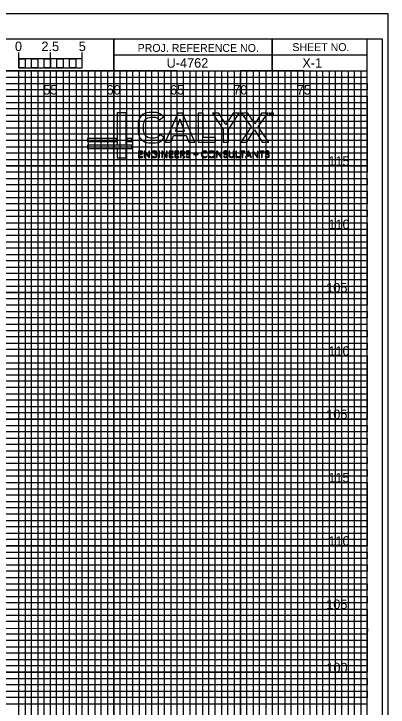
# Model space of a CAD drawing. Extents: x -7 to 162, y -2 to 107.
# Drawn here: x 132.1 to 161.7, y 52.2 to 107 of the extents above; entities that cross this region are included whole.
import ezdxf

# ---------------------------------------------------------------- set-up
doc = ezdxf.new("R2010")
doc.units = 0
for name, color, linetype in [('Old_Level_1', 7, 'Continuous'), ('Prop XS Bar Scale Labels', 7, 'Continuous'), ('Prop XS Elevation Labels', 7, 'Continuous'), ('Prop XS Offset Labels', 7, 'Continuous'), ('Prop XS Project Number', 7, 'Continuous'), ('Prop XS Sheet Number', 7, 'Continuous'), ('Sheet Cross Section CELL', 7, 'Continuous'), ('Sheet Cross Section Grid Major CELL', 7, 'Continuous'), ('Sheet Cross Section Grid Middle CELL', 7, 'Continuous'), ('Sheet Cross Section Grid Minor 1 CELL', 7, 'Continuous'), ('Sheet Cross Section Grid Minor 2 CELL', 7, 'Continuous'), ('Sheet Cross Section Scale CELL', 7, 'Continuous'), ('Sheet Cutting Line CELL', 7, 'Continuous'), ('Sheet DOT Grid CELL', 7, 'Continuous'), ('Sheet Plot Border Inside CELL', 7, 'Continuous'), ('Sheet Plot Border Outside CELL', 7, 'Continuous')]:
    doc.layers.add(name, color=color, linetype=linetype)

msp = doc.modelspace()

# ---------------------------------------------------------------- linework, layer by layer
at = {"layer": 'Old_Level_1'}
for p, q in [((152.376, 99.163), (152.234, 99.163)), ((152.234, 99.163), (152.234, 99.14)), ((152.234, 99.14), (152.293, 99.14)), ((152.293, 99.14), (152.293, 98.986)), ((152.318, 98.986), (152.318, 99.14)), ((152.318, 99.14), (152.376, 99.14)), ((152.376, 99.14), (152.376, 99.163)), ((152.376, 99.14), (152.376, 99.14)), ((152.452, 99.163), (152.412, 99.163)), ((152.412, 99.163), (152.412, 98.986)), ((152.439, 99.135), (152.438, 99.135)), ((152.438, 98.986), (152.439, 99.135)), ((152.439, 99.135), (152.499, 98.986)), ((152.508, 99.027), (152.452, 99.163)), ((152.563, 99.163), (152.508, 99.027)), ((152.515, 98.986), (152.576, 99.135)), ((152.602, 99.163), (152.563, 99.163)), ((152.576, 99.135), (152.575, 99.135)), ((152.576, 99.135), (152.576, 98.986)), ((152.602, 98.986), (152.602, 99.163)), ((143.612, 98.627), (143.928, 98.86)), ((152.293, 98.986), (152.318, 98.986)), ((152.412, 98.986), (152.438, 98.986)), ((152.499, 98.986), (152.515, 98.986)), ((152.576, 98.986), (152.602, 98.986)), ((152.602, 98.986), (152.602, 98.986)), ((143.98, 97.225), (143.644, 97.464)), ((143.358, 96.068), (143.396, 96.106)), ((145.956, 96.077), (146.001, 96.112)), ((147.317, 96.061), (147.362, 96.094)), ((148.928, 96.077), (148.972, 96.112)), ((152.223, 96.077), (152.268, 96.112)), ((145.734, 95.756), (145.688, 95.723)), ((147.374, 95.74), (147.332, 95.77)), ((148.706, 95.756), (148.66, 95.723)), ((152.001, 95.756), (151.955, 95.723))]:
    msp.add_line(p, q, dxfattribs=at)
for points in [[(140.984, 96.665), (140.984, 99.182), (140.267, 99.182), (140.267, 96.665), (140.984, 96.665), (140.984, 96.665)], [(140.984, 96.665), (140.984, 99.182), (140.267, 99.182), (140.267, 96.665), (140.984, 96.665)], [(144.064, 96.876), (144.52, 96.876), (144.726, 97.399), (145.719, 97.399), (145.932, 96.876), (146.397, 96.876), (145.412, 99.163), (145.059, 99.163), (144.064, 96.876)], [(146.652, 96.876), (148.032, 96.876), (148.032, 97.244), (147.06, 97.244), (147.06, 99.163), (146.652, 99.163), (146.652, 96.876)], [(148.64, 96.876), (149.047, 96.876), (149.047, 97.855), (149.906, 99.163), (149.422, 99.163), (148.853, 98.252), (148.291, 99.163), (147.78, 99.163), (148.64, 97.855), (148.64, 96.876)], [(150.023, 96.876), (150.514, 96.876), (151.115, 97.842), (151.719, 96.876), (152.236, 96.876), (151.406, 98.071), (152.155, 99.163), (151.661, 99.163), (151.128, 98.317), (150.588, 99.163), (150.074, 99.163), (150.837, 98.071), (150.023, 96.876)], [(145.576, 97.748), (145.224, 98.679), (144.865, 97.748), (145.576, 97.748)], [(137.929, 97.167), (137.929, 96.928), (140.213, 96.928), (140.213, 97.167), (137.929, 97.167)], [(141.431, 96.928), (141.431, 97.167), (141.028, 97.167), (141.028, 96.928), (141.431, 96.928)], [(137.929, 96.379), (141.431, 96.379), (141.431, 96.619), (137.929, 96.619), (137.929, 96.379)], [(140.267, 95.636), (140.984, 95.636), (140.984, 96.333), (140.267, 96.333), (140.267, 95.636)], [(142.01, 95.897), (142.251, 95.897), (142.251, 95.944), (142.01, 95.944), (142.01, 96.113), (142.268, 96.113), (142.268, 96.16), (141.959, 96.16), (141.959, 95.662), (142.276, 95.662), (142.276, 95.708), (142.01, 95.708), (142.01, 95.897)], [(142.473, 96.16), (142.409, 96.16), (142.409, 95.662), (142.46, 95.662), (142.461, 96.088), (142.758, 95.662), (142.822, 95.662), (142.822, 96.16), (142.771, 96.16), (142.77, 95.738), (142.473, 96.16)], [(143.404, 95.7), (143.404, 95.944), (143.235, 95.944), (143.235, 95.897), (143.354, 95.897), (143.354, 95.731)], [(143.621, 96.16), (143.57, 96.16), (143.57, 95.662), (143.621, 95.662), (143.621, 96.16)], [(143.853, 96.16), (143.789, 96.16), (143.789, 95.662), (143.84, 95.662), (143.841, 96.088), (144.138, 95.662), (144.202, 95.662), (144.202, 96.16), (144.151, 96.16), (144.149, 95.738), (143.853, 96.16)], [(144.42, 95.897), (144.662, 95.897), (144.662, 95.944), (144.42, 95.944), (144.42, 96.113), (144.679, 96.113), (144.679, 96.16), (144.37, 96.16), (144.37, 95.662), (144.687, 95.662), (144.687, 95.708), (144.42, 95.708), (144.42, 95.897)], [(144.871, 95.897), (145.112, 95.897), (145.112, 95.944), (144.871, 95.944), (144.871, 96.113), (145.129, 96.113), (145.129, 96.16), (144.82, 96.16), (144.82, 95.662), (145.137, 95.662), (145.137, 95.708), (144.871, 95.708), (144.871, 95.897)], [(145.424, 96.16), (145.27, 96.16), (145.27, 95.662), (145.321, 95.662), (145.321, 95.893), (145.406, 95.893), (145.542, 95.662), (145.604, 95.662), (145.46, 95.898)], [(145.411, 96.113), (145.321, 96.113), (145.321, 95.94), (145.411, 95.94)], [(146.491, 96.092), (146.449, 96.092), (146.449, 95.933), (146.291, 95.933), (146.291, 95.891), (146.449, 95.891), (146.449, 95.733), (146.491, 95.733), (146.491, 95.891), (146.65, 95.891), (146.65, 95.933), (146.491, 95.933), (146.491, 96.092)], [(148.175, 96.16), (148.112, 96.16), (148.112, 95.662), (148.163, 95.662), (148.164, 96.088), (148.461, 95.662), (148.524, 95.662), (148.524, 96.16), (148.473, 96.16), (148.472, 95.738), (148.175, 96.16)], [(149.159, 95.853), (149.159, 96.16), (149.108, 96.16), (149.108, 95.847)], [(149.473, 95.847), (149.473, 96.16), (149.422, 96.16), (149.422, 95.853)], [(149.683, 96.16), (149.632, 96.16), (149.632, 95.662), (149.915, 95.662), (149.915, 95.708), (149.683, 95.708), (149.683, 96.16)], [(150.177, 96.113), (150.344, 96.113), (150.344, 96.16), (149.96, 96.16), (149.96, 96.113), (150.126, 96.113), (150.126, 95.662), (150.177, 95.662), (150.177, 96.113)], [(150.501, 95.793), (150.755, 95.793), (150.81, 95.662), (150.869, 95.662), (150.653, 96.16), (150.604, 96.16), (150.387, 95.662), (150.446, 95.662), (150.501, 95.793)], [(150.52, 95.839), (150.736, 95.839), (150.628, 96.101), (150.52, 95.839)], [(151.033, 96.16), (150.97, 96.16), (150.97, 95.662), (151.021, 95.662), (151.022, 96.088), (151.319, 95.662), (151.382, 95.662), (151.382, 96.16), (151.332, 96.16), (151.33, 95.738), (151.033, 96.16)], [(151.71, 96.113), (151.877, 96.113), (151.877, 96.16), (151.493, 96.16), (151.493, 96.113), (151.66, 96.113), (151.66, 95.662), (151.71, 95.662), (151.71, 96.113)]]:
    msp.add_lwpolyline(points, dxfattribs=at)
for points in [[(143.928, 98.86), (143.702, 99.121), (143.437, 99.222), (143.127, 99.222), (142.422, 99.222), (141.918, 98.743), (141.918, 98.01), (141.918, 97.296), (142.422, 96.817), (143.127, 96.817), (143.463, 96.817), (143.773, 96.94), (143.98, 97.225)], [(143.644, 97.464), (143.492, 97.27), (143.314, 97.186), (143.13, 97.186), (142.658, 97.186), (142.345, 97.548), (142.345, 98.036), (142.345, 98.491), (142.658, 98.853), (143.13, 98.853), (143.288, 98.853), (143.444, 98.805), (143.612, 98.627)], [(143.396, 96.106), (143.352, 96.15), (143.295, 96.172), (143.216, 96.172), (143.067, 96.172), (142.956, 96.062), (142.956, 95.911), (142.956, 95.759), (143.067, 95.649), (143.216, 95.649), (143.276, 95.649), (143.349, 95.667), (143.404, 95.7)], [(143.354, 95.731), (143.316, 95.71), (143.267, 95.695), (143.216, 95.695), (143.088, 95.695), (143.011, 95.796), (143.011, 95.911), (143.011, 96.025), (143.088, 96.126), (143.216, 96.126), (143.277, 96.126), (143.324, 96.104), (143.358, 96.068)], [(145.411, 95.94), (145.502, 95.94), (145.533, 95.979), (145.533, 96.027), (145.533, 96.075), (145.502, 96.113), (145.411, 96.113)], [(145.46, 95.898), (145.542, 95.905), (145.588, 95.958), (145.588, 96.027), (145.588, 96.116), (145.525, 96.16), (145.424, 96.16)], [(145.688, 95.723), (145.726, 95.671), (145.785, 95.649), (145.845, 95.649), (145.924, 95.649), (146.009, 95.702), (146.009, 95.793), (146.009, 95.973), (145.754, 95.902), (145.754, 96.036), (145.754, 96.099), (145.808, 96.126), (145.86, 96.126), (145.902, 96.126), (145.935, 96.11), (145.956, 96.077)], [(146.001, 96.112), (145.961, 96.157), (145.916, 96.172), (145.86, 96.172), (145.779, 96.172), (145.699, 96.127), (145.699, 96.031), (145.699, 95.849), (145.954, 95.927), (145.954, 95.786), (145.954, 95.728), (145.897, 95.695), (145.847, 95.695), (145.795, 95.695), (145.755, 95.719), (145.734, 95.756)], [(147.362, 96.094), (147.318, 96.149), (147.251, 96.172), (147.189, 96.172), (147.041, 96.172), (146.93, 96.062), (146.93, 95.911), (146.93, 95.759), (147.041, 95.649), (147.189, 95.649), (147.272, 95.649), (147.341, 95.689), (147.374, 95.74)], [(147.332, 95.77), (147.295, 95.712), (147.241, 95.695), (147.189, 95.695), (147.061, 95.695), (146.985, 95.796), (146.985, 95.911), (146.985, 96.025), (147.061, 96.126), (147.189, 96.126), (147.242, 96.126), (147.298, 96.093), (147.317, 96.061)], [(147.718, 95.649), (147.569, 95.649), (147.458, 95.759), (147.458, 95.911), (147.458, 96.062), (147.569, 96.172), (147.718, 96.172), (147.866, 96.172), (147.977, 96.062), (147.977, 95.911), (147.977, 95.759), (147.866, 95.649), (147.718, 95.649), (147.718, 95.649), (147.718, 95.649), (147.718, 95.649)], [(147.718, 96.126), (147.59, 96.126), (147.513, 96.025), (147.513, 95.911), (147.513, 95.796), (147.59, 95.695), (147.718, 95.695), (147.846, 95.695), (147.922, 95.796), (147.922, 95.911), (147.922, 96.025), (147.846, 96.126), (147.718, 96.126), (147.718, 96.126), (147.718, 96.126), (147.718, 96.126)], [(148.66, 95.723), (148.698, 95.671), (148.756, 95.649), (148.817, 95.649), (148.896, 95.649), (148.981, 95.702), (148.981, 95.793), (148.981, 95.973), (148.725, 95.902), (148.725, 96.036), (148.725, 96.099), (148.78, 96.126), (148.832, 96.126), (148.874, 96.126), (148.906, 96.11), (148.928, 96.077)], [(148.972, 96.112), (148.933, 96.157), (148.888, 96.172), (148.832, 96.172), (148.751, 96.172), (148.671, 96.127), (148.671, 96.031), (148.671, 95.849), (148.926, 95.927), (148.926, 95.786), (148.926, 95.728), (148.869, 95.695), (148.819, 95.695), (148.767, 95.695), (148.727, 95.719), (148.706, 95.756)], [(149.108, 95.847), (149.108, 95.764), (149.141, 95.649), (149.29, 95.649), (149.44, 95.649), (149.473, 95.764), (149.473, 95.847)], [(149.422, 95.853), (149.422, 95.71), (149.328, 95.695), (149.29, 95.695), (149.252, 95.695), (149.159, 95.71), (149.159, 95.853)], [(151.955, 95.723), (151.993, 95.671), (152.052, 95.649), (152.112, 95.649), (152.191, 95.649), (152.276, 95.702), (152.276, 95.793), (152.276, 95.973), (152.021, 95.902), (152.021, 96.036), (152.021, 96.099), (152.075, 96.126), (152.127, 96.126), (152.169, 96.126), (152.202, 96.11), (152.223, 96.077)], [(152.268, 96.112), (152.228, 96.157), (152.183, 96.172), (152.127, 96.172), (152.046, 96.172), (151.966, 96.127), (151.966, 96.031), (151.966, 95.849), (152.221, 95.927), (152.221, 95.786), (152.221, 95.728), (152.164, 95.695), (152.114, 95.695), (152.062, 95.695), (152.022, 95.719), (152.001, 95.756)]]:
    msp.add_open_spline(points, degree=3, dxfattribs=at)
at = {"layer": 'Sheet Cross Section CELL'}
for p, q in [((152.5, 105), (152.5, 102.5)), ((152.5, 102.5), (152.5, 105)), ((140, 103.75), (140, 102.5)), ((160, 103.745), (140, 103.745)), ((140, 102.5), (160, 102.5))]:
    msp.add_line(p, q, dxfattribs=at)
for points in [[(160, 105), (0, 105), (0, 0), (160, 0)], [(140, 105), (130, 105), (130, 102.515), (140, 102.515)], [(160, 105), (140, 105), (140, 102.5), (160, 102.5)]]:
    msp.add_lwpolyline(points, close=True, dxfattribs=at)
at = {"layer": 'Sheet Cross Section Grid Major CELL'}
for p, q in [((135, 0), (135, 102.5)), ((145, 102.5), (140, 102.5)), ((140, 102.5), (140, 0)), ((145, 0), (145, 102.5)), ((155, 102.5), (150, 102.5)), ((150, 102.5), (150, 0)), ((155, 0), (155, 102.5))]:
    msp.add_line(p, q, dxfattribs=at)
for points in [[(0, 100), (160, 100), (160, 95), (0, 95)], [(0, 90), (160, 90), (160, 85), (0, 85)], [(0, 80), (160, 80), (160, 75), (0, 75)], [(0, 70), (160, 70), (160, 65), (0, 65)], [(0, 60), (160, 60), (160, 55), (0, 55)]]:
    msp.add_lwpolyline(points, dxfattribs=at)
at = {"layer": 'Sheet Cross Section Grid Middle CELL'}
for points in [[(127.5, 0), (127.5, 105), (129.965, 105), (130, 105), (130, 102.5), (132.495, 102.5), (132.495, 0)], [(0, 102.5), (137.5, 102.5)], [(137.5, 0), (137.5, 102.5), (142.5, 102.5), (142.5, 0)], [(147.5, 0), (147.5, 102.5), (152.5, 102.5), (152.5, 0)], [(157.5, 0), (157.5, 102.5)], [(0, 92.5), (160, 92.5), (160, 97.5), (0, 97.5)], [(0, 82.5), (160, 82.5), (160, 87.5), (0, 87.5)], [(0, 72.5), (160, 72.5), (160, 77.5), (0, 77.5)], [(0, 62.5), (160, 62.5), (160, 67.5), (0, 67.5)], [(0, 52.5), (160, 52.5), (160, 57.5), (0, 57.5)]]:
    msp.add_lwpolyline(points, dxfattribs=at)
at = {"layer": 'Sheet Cross Section Grid Minor 1 CELL'}
msp.add_line((0, 102), (160, 102), dxfattribs=at)
for points in [[(0, 101.5), (135, 101.5), (160, 101.5), (160, 101), (0, 101)], [(0, 100.5), (160, 100.5), (160, 99.5), (0, 99.5)], [(0, 99), (160, 99), (160, 98.5), (0, 98.49)], [(0, 98), (160, 98), (160, 97), (0, 97)], [(0, 96.5), (160, 96.5), (160, 96), (0, 96)], [(0, 95.5), (160, 95.5), (160, 94.5), (0, 94.5)], [(0, 94), (160, 94), (160, 93.5), (0, 93.5)], [(0, 93), (160, 93), (160, 92), (0, 92)], [(0, 91.5), (160, 91.5), (160, 91), (0, 91)], [(0, 90.5), (160, 90.5), (160, 89.5), (0, 89.5)], [(0, 89), (160, 89), (160, 88.5), (0, 88.5)], [(0, 88), (160, 88), (160, 86.975), (160, 86.5), (160, 86), (0, 86)], [(0, 87), (160, 87), (160, 86.5), (0, 86.5)], [(0, 85.5), (160, 85.5), (160, 84.5), (0, 84.515)], [(0, 84.515), (160, 84.5), (160, 84), (0, 84)], [(0, 83.5), (160, 83.5), (160, 83), (0, 83)], [(0, 82), (160, 82), (160, 81.5), (0, 81.5)], [(0, 81), (160, 81), (160, 80.5), (0, 80.5)], [(-0.035, 79.445), (160, 79.445), (160, 78.94), (-0.035, 78.94)], [(0, 78.5), (160, 78.5), (160, 78), (0, 78)], [(0, 77), (160, 77), (160, 76.5), (0, 76.5)], [(0, 76), (160, 76), (160, 75.5), (0, 75.5)], [(0, 74.5), (160, 74.5), (160, 74), (0, 74)], [(0, 73.5), (160, 73.5), (160, 73), (0, 73)], [(0, 72), (160, 72), (160, 71.5), (0, 71.5)], [(0, 71), (160, 71), (160, 70.5), (0, 70.5)], [(0, 69.5), (160, 69.5), (159.995, 68.99), (0, 69)], [(0, 68.5), (160, 68.5), (160, 68), (0, 68)], [(0, 67), (160, 67), (160, 66.5), (0, 66.5)], [(0, 66), (160, 66), (160, 65.5), (0, 65.5)], [(0, 64.5), (160, 64.5), (160, 64), (0, 64)], [(0, 63.5), (160, 63.5), (160, 63), (0, 63)], [(0, 62), (160, 62), (160, 61.5), (0, 61.5)], [(0, 61), (160, 61), (160, 60.5), (0, 60.5)], [(0, 59.5), (160, 59.5), (160, 59), (0, 59)], [(0, 58.495), (160.035, 58.455), (160, 58), (0, 58)], [(0, 57), (160, 57), (160, 56.5), (0, 56.5)], [(0, 56), (160, 56), (160, 55.5), (0, 55.5)], [(0, 54.5), (160, 54.5), (160, 54), (0, 54)], [(0, 53.5), (160, 53.5), (160, 53), (0, 53)]]:
    msp.add_lwpolyline(points, dxfattribs=at)
at = {"layer": 'Sheet Cross Section Grid Minor 2 CELL'}
for p, q in [((133.5, 102.5), (133.005, 102.5)), ((133.005, 102.5), (133.005, 0)), ((133.5, 0), (133.5, 102.5)), ((134.5, 102.5), (134, 102.5)), ((134, 102.5), (134, 0)), ((134.5, 0), (134.5, 102.5))]:
    msp.add_line(p, q, dxfattribs=at)
for points in [[(135, 0), (135.49, 0), (135.49, 102.5), (136, 102.5), (136, 0)], [(136, 0), (136.5, 0), (136.5, 102.5), (137.025, 102.5), (137.025, 0)], [(137.5, 0), (138, 0), (138, 102.5), (138.5, 102.5), (138.5, 0)], [(138.5, 0), (139, 0), (139, 102.5), (139.5, 102.5), (139.5, 0)], [(140, 0), (140.5, 0), (140.5, 102.5), (141, 102.5), (141, 0)], [(141, 0), (141.5, 0), (141.5, 102.5), (142, 102.5), (142, 0)], [(142.5, 0), (143, 0), (143, 102.5), (143.5, 102.5), (143.5, 0)], [(143.5, 0), (144, 0), (144, 102.5), (144.5, 102.5), (144.5, 0)], [(145, 0), (145.5, 0), (145.5, 102.5), (146, 102.5), (146, 0)], [(146, 0), (146.5, 0), (146.5, 102.5), (147, 102.5), (147, 0)], [(147.5, 0), (148, 0), (148, 102.5), (148.5, 102.5), (148.5, 0)], [(148.5, 0), (149, 0), (149, 102.5), (149.5, 102.5), (149.5, 0)], [(150, 0), (150.5, 0), (150.5, 102.5), (151, 102.5), (151, 0)], [(151, 0), (151.5, 0), (151.5, 102.5), (152, 102.5), (152, 0)], [(152.5, 0), (153, 0), (153, 102.5), (153.5, 102.5), (153.5, 0)], [(153.5, 0), (154, 0), (154, 102.5), (154.5, 102.5), (154.5, 0)], [(155, 0), (155.5, 0), (155.5, 102.5), (156, 102.5), (156, 0)], [(156, 0), (156.5, 0), (156.5, 102.5), (157, 102.5), (157, 0)], [(157.5, 0), (158, 0), (158, 102.5), (158.5, 102.5), (158.5, 0)], [(158.5, 0), (159, 0), (159, 102.5), (159.5, 102.5), (159.5, 0)]]:
    msp.add_lwpolyline(points, dxfattribs=at)
at = {"layer": 'Sheet Cross Section Scale CELL'}
for p, q in [((132.5, 102.745), (132.5, 103.95)), ((132.5, 103.45), (132.5, 103.95)), ((135, 102.745), (135, 103.95)), ((137.5, 102.745), (137.5, 103.95)), ((137.5, 103.45), (137.5, 103.95))]:
    msp.add_line(p, q, dxfattribs=at)
for points in [[(137.5, 103.45), (132.5, 103.45), (132.5, 102.745), (137.5, 102.745)], [(132.5, 103.45), (133, 103.45), (133, 102.745), (132.5, 102.745)], [(133.5, 103.45), (134, 103.45), (134, 102.745), (133.5, 102.745)], [(134.5, 103.45), (135, 103.45), (135, 102.745), (134.5, 102.745)], [(135.5, 103.45), (136, 103.45), (136, 102.745), (135.5, 102.745)], [(136.5, 103.45), (137, 103.45), (137, 102.745), (136.5, 102.745)]]:
    msp.add_lwpolyline(points, close=True, dxfattribs=at)
at = {"layer": 'Sheet Cutting Line CELL'}
msp.add_line((161.65, 107), (-6.7, 107), dxfattribs=at)
at = {"layer": 'Sheet DOT Grid CELL'}
for p, q in [((135, 0), (135, 102.343)), ((140, 0), (140, 102.343)), ((145, 0), (145, 102.343)), ((150, 0), (150, 102.343)), ((155, 0), (155, 102.343)), ((0, 100), (160, 100)), ((0, 95), (160, 95)), ((0, 90), (160, 90)), ((0, 85), (160, 85)), ((0, 80), (160, 80)), ((0, 75), (160, 75)), ((0, 70), (160, 70)), ((0, 65), (160, 65)), ((0, 60), (160, 60)), ((0, 55), (160, 55))]:
    msp.add_line(p, q, dxfattribs=at)
at = {"layer": 'Sheet Plot Border Inside CELL'}
msp.add_lwpolyline([(-5.4, -0.5), (161.2, -0.5), (161.2, 105), (-5.4, 105)], close=True, dxfattribs=at)
at = {"layer": 'Sheet Plot Border Outside CELL'}
msp.add_lwpolyline([(-6.7, -2.5), (161.65, -2.5), (161.65, 107), (-6.7, 107)], close=True, dxfattribs=at)

# ---------------------------------------------------------------- texts
at = {"layer": 'Prop XS Bar Scale Labels'}
for s, p in [('2.5', (134.292, 104.06)), ('5', (137.237, 104.06))]:
    msp.add_text(s, height=0.75, dxfattribs=at).set_placement(p)
at = {"layer": 'Prop XS Elevation Labels'}
for s, p in [('115', (156.93, 95)), ('110', (156.939, 90)), ('105', (156.765, 85)), ('110', (156.939, 80)), ('105', (156.765, 75)), ('115', (156.93, 70)), ('110', (156.939, 65)), ('105', (156.765, 60)), ('100', (156.774, 55))]:
    msp.add_text(s, height=0.75, dxfattribs=at).set_placement(p)
at = {"layer": 'Prop XS Offset Labels'}
for s, p in [('55', (134.441, 100.625)), ('60', (139.429, 100.625)), ('65', (144.441, 100.625)), ('70', (149.429, 100.625)), ('75', (154.441, 100.625))]:
    msp.add_text(s, height=0.75, dxfattribs=at).set_placement(p)
at = {"layer": 'Prop XS Project Number'}
msp.add_text('U-4762', height=0.75, dxfattribs=at).set_placement((144.171, 102.75))
at = {"layer": 'Prop XS Sheet Number'}
msp.add_text('X-1', height=0.75, dxfattribs=at).set_placement((154.882, 102.75))
at = {"layer": 'Sheet Cross Section CELL'}
for s, height, p in [('PROJ. REFERENCE NO.', 0.62499, (141.885, 103.995)), ('SHEET NO.', 0.625, (154.095, 104.06))]:
    msp.add_text(s, height=height, dxfattribs=at).set_placement(p)
at = {"layer": 'Sheet Cross Section Scale CELL'}
msp.add_text('0', height=0.75, dxfattribs=at).set_placement((132.205, 104.06))

doc.saveas('drawing.dxf')
